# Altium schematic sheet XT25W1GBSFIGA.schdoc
size 127 x 101 mm
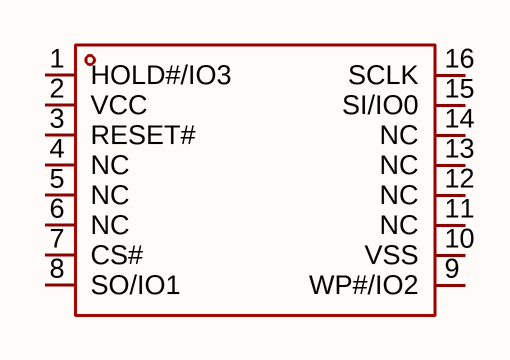
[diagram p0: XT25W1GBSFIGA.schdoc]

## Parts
U?  xt25w1gbsfiga  [SOP-16_L10.3-W7.5-P1.27-LS10.3-BL]  (value not drawn)

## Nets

Not connected (* = marked no-connect by the designer): U? 1(HOLD#/IO3) 2(VCC) 3(RESET#) 4(NC) 5(NC) 6(NC) 7(CS#) 8(SO/IO1) 9(WP#/IO2) 10(VSS) 11(NC) 12(NC) 13(NC) 14(NC) 15(SI/IO0) 16(SCLK)

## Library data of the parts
U? = xt25w1gbsfiga: 接口类型:SPI;存储容量:1Gbit;时钟频率(fc):104MHz;; Manufacturer: XTX(芯天下); AddInBom: yes; ModelId: 89cbb1eeec7e4dc89e56d8a524192cc7; ModelTransform: 405.511,405.511,0,0,0,0,0,0,0; Interface: SPI; Memory Size: 1Gbit; Clock Frequency: 104MHz; Voltage - Supply: 1.65V~3.6V; Standby Supply Current: 0.2uA; Program / Erase Cycles: 100000次; Page Programming Time (Tpp): 300us; Block Erase Time(tBE): 380ms@(32KB); Data Retention - TDR (Year): 10年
